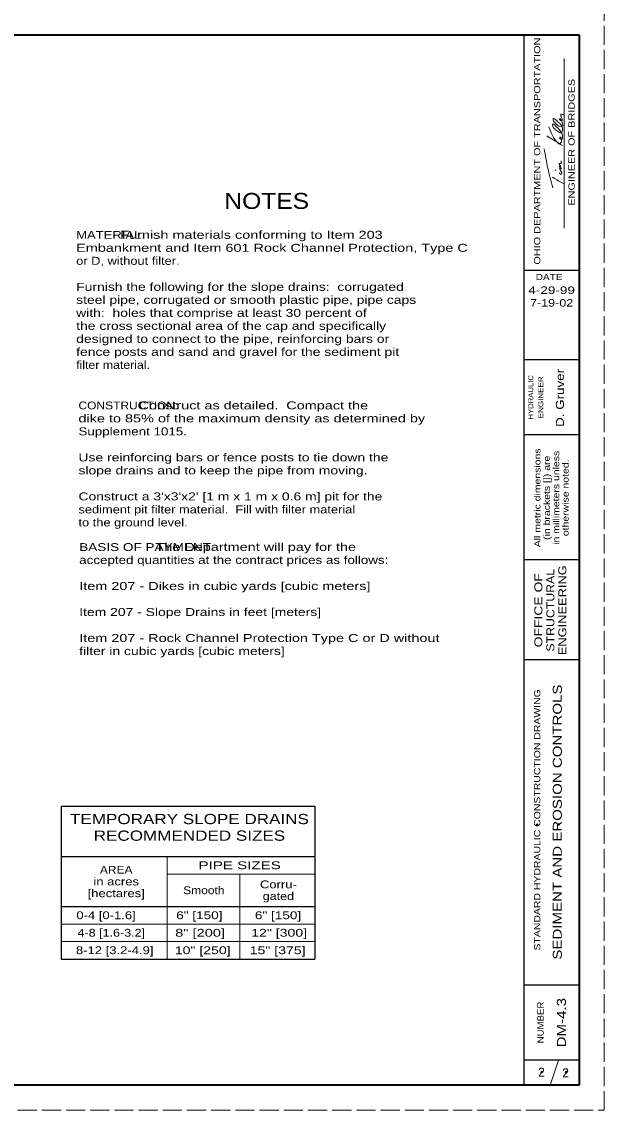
# Model space of a CAD drawing. Extents: x 1043.1 to 1101.1, y 672.4 to 716.4.
# Drawn here: x 1065.49 to 1077.14, y 672.4 to 694.15 of the extents above; entities that cross this region are included whole.
import ezdxf
from ezdxf.enums import TextEntityAlignment as Align

# ---------------------------------------------------------------- set-up
doc = ezdxf.new("R2010")
doc.units = 0
doc.header["$LTSCALE"] = 0.064
doc.header["$PDMODE"] = 32
doc.header["$PDSIZE"] = 0.032
doc.linetypes.add('LONG_DASHED', pattern=[7.5, 6, -1.5])
doc.layers.add('1', color=7, linetype='Continuous', lineweight=13)

msp = doc.modelspace()

# ---------------------------------------------------------------- linework, layer by layer
at = {"layer": '1', "lineweight": 25}
for p, q in [((1045.14425, 693.89508), (1076.64425, 693.89508)), ((1075.54425, 672.89508), (1075.54425, 693.89508)), ((1076.64425, 693.89508), (1076.64425, 672.89508)), ((1076.64425, 689.17925), (1075.54425, 689.17925)), ((1076.64425, 687.39508), (1075.54425, 687.39508)), ((1076.64425, 685.89508), (1075.54425, 685.89508)), ((1076.64425, 683.39508), (1075.54425, 683.39508)), ((1076.64425, 681.39508), (1075.54425, 681.39508)), ((1066.282, 678.47408), (1071.35575, 678.47408)), ((1066.282, 678.47408), (1066.282, 675.41792)), ((1071.35575, 678.47408), (1071.35575, 675.41792)), ((1066.282, 677.46667), (1071.35575, 677.46667)), ((1066.282, 676.46733), (1071.35575, 676.46733)), ((1066.282, 675.41792), (1071.35575, 675.41792)), ((1076.64425, 674.89508), (1075.54425, 674.89508)), ((1076.64425, 673.39508), (1075.54425, 673.39508))]:
    msp.add_line(p, q, dxfattribs=at)
at = {"layer": '1', "lineweight": 40}
for p, q in [((1045.14425, 693.89508), (1076.64425, 693.89508)), ((1045.14425, 693.89508), (1076.64425, 693.89508)), ((1076.64425, 693.89508), (1076.64425, 672.89508))]:
    msp.add_line(p, q, dxfattribs=at)
at = {"layer": '1'}
for p, q in [((1076.343, 690.02608), (1076.343, 693.41617)), ((1076.1755, 691.177), (1076.16533, 691.19625)), ((1068.40283, 677.46667), (1068.40283, 675.41792)), ((1068.40283, 677.11692), (1071.35575, 677.11692)), ((1069.85675, 677.11692), (1069.85675, 675.41792)), ((1066.282, 676.1175), (1071.35575, 676.1175)), ((1066.282, 675.76775), (1071.35575, 675.76775)), ((1076.06092, 672.89508), (1076.22758, 673.39508))]:
    msp.add_line(p, q, dxfattribs=at)
at = {"layer": '1', "linetype": 'LONG_DASHED'}
msp.add_lwpolyline([(1043.14425, 672.39508), (1077.14425, 672.39508), (1077.14425, 694.39508), (1043.14425, 694.39508)], close=True, dxfattribs=at)
at = {"layer": '1', "lineweight": 25}
msp.add_lwpolyline([(1076.64425, 672.89508), (1045.14425, 672.89508), (1045.14425, 693.89508)], dxfattribs=at)
at = {"layer": '1', "lineweight": 40}
msp.add_lwpolyline([(1076.64425, 672.89508), (1045.14425, 672.89508), (1045.14425, 693.89508)], dxfattribs=at)
msp.add_lwpolyline([(1076.64425, 672.89508), (1045.14425, 672.89508), (1045.14425, 693.89508)], dxfattribs=at)
at = {"layer": '1'}
for points in [[(1076.03608, 692.05208), (1076.21925, 691.72375), (1076.23442, 691.71317), (1076.24458, 691.71317), (1076.2765, 691.73683), (1076.29158, 691.771), (1076.28658, 691.82225), (1076.26967, 691.84408), (1076.25617, 691.84408), (1076.25442, 691.83108), (1076.26458, 691.81592), (1076.27808, 691.8075), (1076.29317, 691.8075), (1076.30833, 691.82908), (1076.31175, 691.84842), (1076.3015, 691.90375), (1076.21925, 692.02417), (1076.17375, 692.06883), (1076.13683, 692.10342), (1076.11167, 692.10558), (1076.11342, 692.067), (1076.13858, 692.02825), (1076.20583, 691.96592), (1076.24792, 691.9405), (1076.28158, 691.936), (1076.30492, 691.962), (1076.31175, 691.99617), (1076.30667, 692.02192), (1076.2765, 692.09508), (1076.24625, 692.12708), (1076.18567, 692.1805), (1076.157, 692.20633), (1076.1235, 692.22158), (1076.12008, 692.19358), (1076.13017, 692.16775), (1076.18733, 692.10783), (1076.258, 692.06058), (1076.31, 692.06292), (1076.30833, 692.12058), (1076.2965, 692.1635), (1076.28317, 692.18925), (1076.273, 692.2), (1076.24958, 692.215), (1076.25133, 692.19792), (1076.28658, 692.17642), (1076.3015, 692.18717), (1076.28842, 692.24083), (1076.27983, 692.26875), (1076.2765, 692.28142), (1076.2765, 692.29425), (1076.2765, 692.30292), (1076.3015, 692.30075), (1076.32692, 692.30075)], [(1075.99725, 691.86983), (1076.221, 691.73233), (1076.30667, 691.67667)], [(1076.1135, 690.83283), (1076.01483, 691.22808), (1075.94358, 691.61042)], [(1076.24458, 691.13175), (1076.25283, 691.12108), (1076.29, 691.10817), (1076.29475, 691.14058), (1076.26967, 691.177), (1076.25442, 691.21325), (1076.25442, 691.2325), (1076.26967, 691.22625), (1076.27983, 691.21542), (1076.29, 691.21108), (1076.26633, 691.24325), (1076.25442, 691.25825), (1076.25133, 691.27558), (1076.27475, 691.269), (1076.26633, 691.27767), (1076.24117, 691.3055), (1076.25133, 691.32067), (1076.26808, 691.32267), (1076.2765, 691.32067), (1076.28658, 691.342), (1076.27983, 691.36992)], [(1076.32867, 690.91725), (1076.1235, 691.03725), (1076.10792, 691.04767)]]:
    msp.add_spline(points, degree=3, dxfattribs=at)
for p in [(1075.80167, 678.10108), (1076.2345, 678.10842), (1075.89233, 673.15883), (1076.38075, 673.15783)]:
    msp.add_point(p, dxfattribs=at)

# ---------------------------------------------------------------- texts
for s, height, width, p in [('OHIO DEPARTMENT OF TRANSPORTATION', 0.125, 1.3, (1075.86417, 691.56733)), ('ENGINEER OF BRIDGES', 0.125, 1.3, (1076.5525, 691.74412)), ('D. Gruver', 0.16, 1.25, (1076.33758, 686.63433)), ('HYDRAULIC', 0.1, 1.15, (1075.72333, 686.64617)), ('ENGINEER', 0.1, 1.2, (1075.92425, 686.64621)), ('All metric dimensions', 0.125, 1.25, (1075.86808, 684.63717)), ('(in brackets []) are', 0.125, 1.25, (1076.05558, 684.63717)), ('in millimeters unless', 0.125, 1.25, (1076.24308, 684.63721)), ('otherwise noted.', 0.125, 1.25, (1076.43058, 684.63717)), ('STRUCTURAL', 0.16, 1.15, (1076.146, 682.38954)), ('ENGINEERING', 0.16, 1.2, (1076.386, 682.38963)), ('OFFICE OF', 0.16, 1.3, (1075.906, 682.38954)), ('SEDIMENT AND EROSION CONTROLS', 0.18, 1.25, (1076.29542, 678.15525)), ('STANDARD HYDRAULIC CONSTRUCTION DRAWING', 0.125, 1.25, (1075.86417, 678.19912)), ('NUMBER', 0.125, 1.15, (1075.93125, 674.14917)), ('DM-4.3', 0.18, 1.25, (1076.37758, 674.14542))]:
    msp.add_text(s, height=height, rotation=90, dxfattribs=dict(at, width=width)).set_placement(p, align=Align.CENTER)
for s, height, width, p in [('NOTES', 0.32, 1.15, (1070.39179, 690.41183)), ('DATE', 0.125, 1.2, (1076.04096, 688.98783)), ('4-29-99', 0.15, 1.35, (1076.09125, 688.71233)), ('7-19-02', 0.15, 1.25, (1076.09129, 688.45925)), ('TEMPORARY SLOPE DRAINS', 0.2042, 1.25, (1068.84562, 678.11392)), ('RECOMMENDED SIZES', 0.2042, 1.25, (1068.84571, 677.78217)), ('PIPE SIZES', 0.156, 1.45, (1069.84975, 677.21375)), ('AREA', 0.156, 1.15, (1067.38, 677.12367)), ('in acres', 0.156, 1.25, (1067.38004, 676.889)), ('Corru-', 0.156, 1.25, (1070.62492, 676.83133)), ('[hectares]', 0.156, 1.25, (1067.38, 676.65433)), ('Smooth', 0.156, 1.15, (1069.1335, 676.714)), ('gated', 0.156, 1.2, (1070.62492, 676.59667)), ('0-4 [0-1.6]', 0.156, 1.25, (1067.17692, 676.21433)), ('6" [150]', 0.156, 1.3, (1069.04325, 676.21442)), ('6" [150]', 0.156, 1.3, (1070.61742, 676.21433)), ('4-8 [1.6-3.2]', 0.156, 1.2, (1067.28204, 675.86458)), ('8" [200]', 0.156, 1.4, (1069.05838, 675.86458)), ('12" [300]', 0.156, 1.35, (1070.64008, 675.8645)), ('8-12 [3.2-4.9]', 0.156, 1.25, (1067.34975, 675.51483)), ('10" [250]', 0.156, 1.35, (1069.11092, 675.51475)), ('15" [375]', 0.156, 1.35, (1070.60987, 675.51475))]:
    msp.add_text(s, height=height, dxfattribs=dict(at, width=width)).set_placement(p, align=Align.CENTER)
for s, height, width, p in [('MATERIAL:', 0.156, 1.25, (1066.57917, 689.81433)), ('           Furnish materials conforming to Item 203', 0.16, 1.35, (1066.57917, 689.81433)), ('Embankment and Item 601 Rock Channel Protection, Type C', 0.16, 1.35, (1066.57917, 689.55433)), ('or D, without filter.', 0.16, 1.2, (1066.57917, 689.29433)), ('Furnish the following for the slope drains:  corrugated', 0.16, 1.3, (1066.57917, 688.77433)), ('steel pipe, corrugated or smooth plastic pipe, pipe caps ', 0.16, 1.3, (1066.57917, 688.51433)), ('with:  holes that comprise at least 30 percent of ', 0.16, 1.3, (1066.57917, 688.25433)), ('the cross sectional area of the cap and specifically', 0.16, 1.3, (1066.57917, 687.99433)), ('designed to connect to the pipe, reinforcing bars or', 0.16, 1.3, (1066.57917, 687.73433)), ('fence posts and sand and gravel for the sediment pit', 0.16, 1.3, (1066.57917, 687.47433)), ('filter material.', 0.16, 1.15, (1066.57917, 687.21433)), ('CONSTRUCTION:', 0.156, 1.15, (1066.62483, 686.40525)), ('               Construct as detailed.  Compact the', 0.16, 1.35, (1066.62483, 686.40525)), ('dike to 85% of the maximum density as determined by', 0.16, 1.35, (1066.62483, 686.14525)), ('Supplement 1015.', 0.16, 1.25, (1066.62483, 685.88525)), ('Use reinforcing bars or fence posts to tie down the', 0.16, 1.3, (1066.62483, 685.36525)), ('slope drains and to keep the pipe from moving.', 0.16, 1.3, (1066.62483, 685.10525)), ("Construct a 3'x3'x2' [1 m x 1 m x 0.6 m] pit for the", 0.16, 1.3, (1066.62483, 684.58525)), ('sediment pit filter material.  Fill with filter material', 0.16, 1.2, (1066.62483, 684.32525)), ('to the ground level.', 0.16, 1.2, (1066.62483, 684.06525)), ('BASIS OF PAYMENT:', 0.156, 1.3, (1066.64008, 683.57458)), ('                   The Department will pay for the', 0.16, 1.35, (1066.64008, 683.57458)), ('accepted quantities at the contract prices as follows:', 0.16, 1.25, (1066.64008, 683.31458)), ('Item 207 - Dikes in cubic yards [cubic meters]', 0.16, 1.35, (1066.64008, 682.79458)), ('Item 207 - Slope Drains in feet [meters]', 0.16, 1.3, (1066.64008, 682.27458)), ('Item 207 - Rock Channel Protection Type C or D without', 0.16, 1.35, (1066.64008, 681.75458)), ('filter in cubic yards [cubic meters]', 0.16, 1.3, (1066.64008, 681.49458))]:
    msp.add_text(s, height=height, dxfattribs=dict(at, width=width)).set_placement(p)
for p in [(1075.88871, 673.06517), (1076.37154, 673.05258)]:
    msp.add_text('2', height=0.18, dxfattribs=at).set_placement(p, align=Align.CENTER)

doc.saveas('drawing.dxf')
